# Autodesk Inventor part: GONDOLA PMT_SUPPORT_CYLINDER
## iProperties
Shininess: 64.0
Length Units: 11272
Angle Units: 11279
Time Units: 11290
Mass Units: 11286
Length Display Precision: 3
Angle Display Precision: 2
Compacted: True
Part Number: GONDOLA PMT_SUPPORT_CYLINDER
Document SubType Name: Modeling
Created: 2004-08
Designer: John Blackburn
Manufacturer: Standard
Standards Organization: Custom
Density: 0.0
Volumn: 0.0
Area: 0.0
PropertySet Name: Model Information
Control State: 0
Master: False
Checked Out: False
Author: John Blackburn
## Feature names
1. ExtrusionBlind1
2. AM_HOLE_SI0030_1 [Hole]
3. Hole1
4. Hole2
5. Polar Pattern1 [Circular Pattern]
